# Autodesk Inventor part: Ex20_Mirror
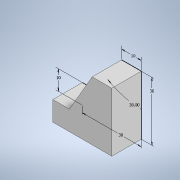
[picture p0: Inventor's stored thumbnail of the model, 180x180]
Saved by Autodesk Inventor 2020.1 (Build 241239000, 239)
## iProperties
Created: 2019-11
Part Number: Ex20_Mirror
Material: Generic
Document SubType Name: Modeling
Designer: Synergysoft Dell02
Density: 1 g/cm^3
Appearance: Default
Author: Synergysoft Dell02
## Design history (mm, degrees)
sketch "Sketch1"
  geometry: L1 (0, 30)-(-10, 30); L2 (-10, 30)-(-21.547, 10); L3 (-21.547, 10)-(-30, 10); L4 (-30, 10)-(-30, 0); L5 (-30, 0)-(0, 0); L6 (0, 0)-(0, 30)
  constraints: 12 end point, 3 perpendicular, 1 horizontal, 1 parallel
  dimensions: "d0" = 10 distance between parallel lines of L5 L3; "d1" = 30 deg angle of L6 L2; "d2" = 30 distance of L5.end L1.start; "d3" = 30 distance between parallel lines of L6 L4; "d4" = 10 distance of L1.start L1.end
extrude "Extrusion1" new body sketch "Sketch1" distance "d5" = 15; taper "d6" = 0 deg
body "Solid1"
